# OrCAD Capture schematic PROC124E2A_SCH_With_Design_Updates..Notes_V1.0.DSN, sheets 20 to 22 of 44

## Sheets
20 18. eMMC FLASH: size C; title: eMMC FLASH INTERFACE
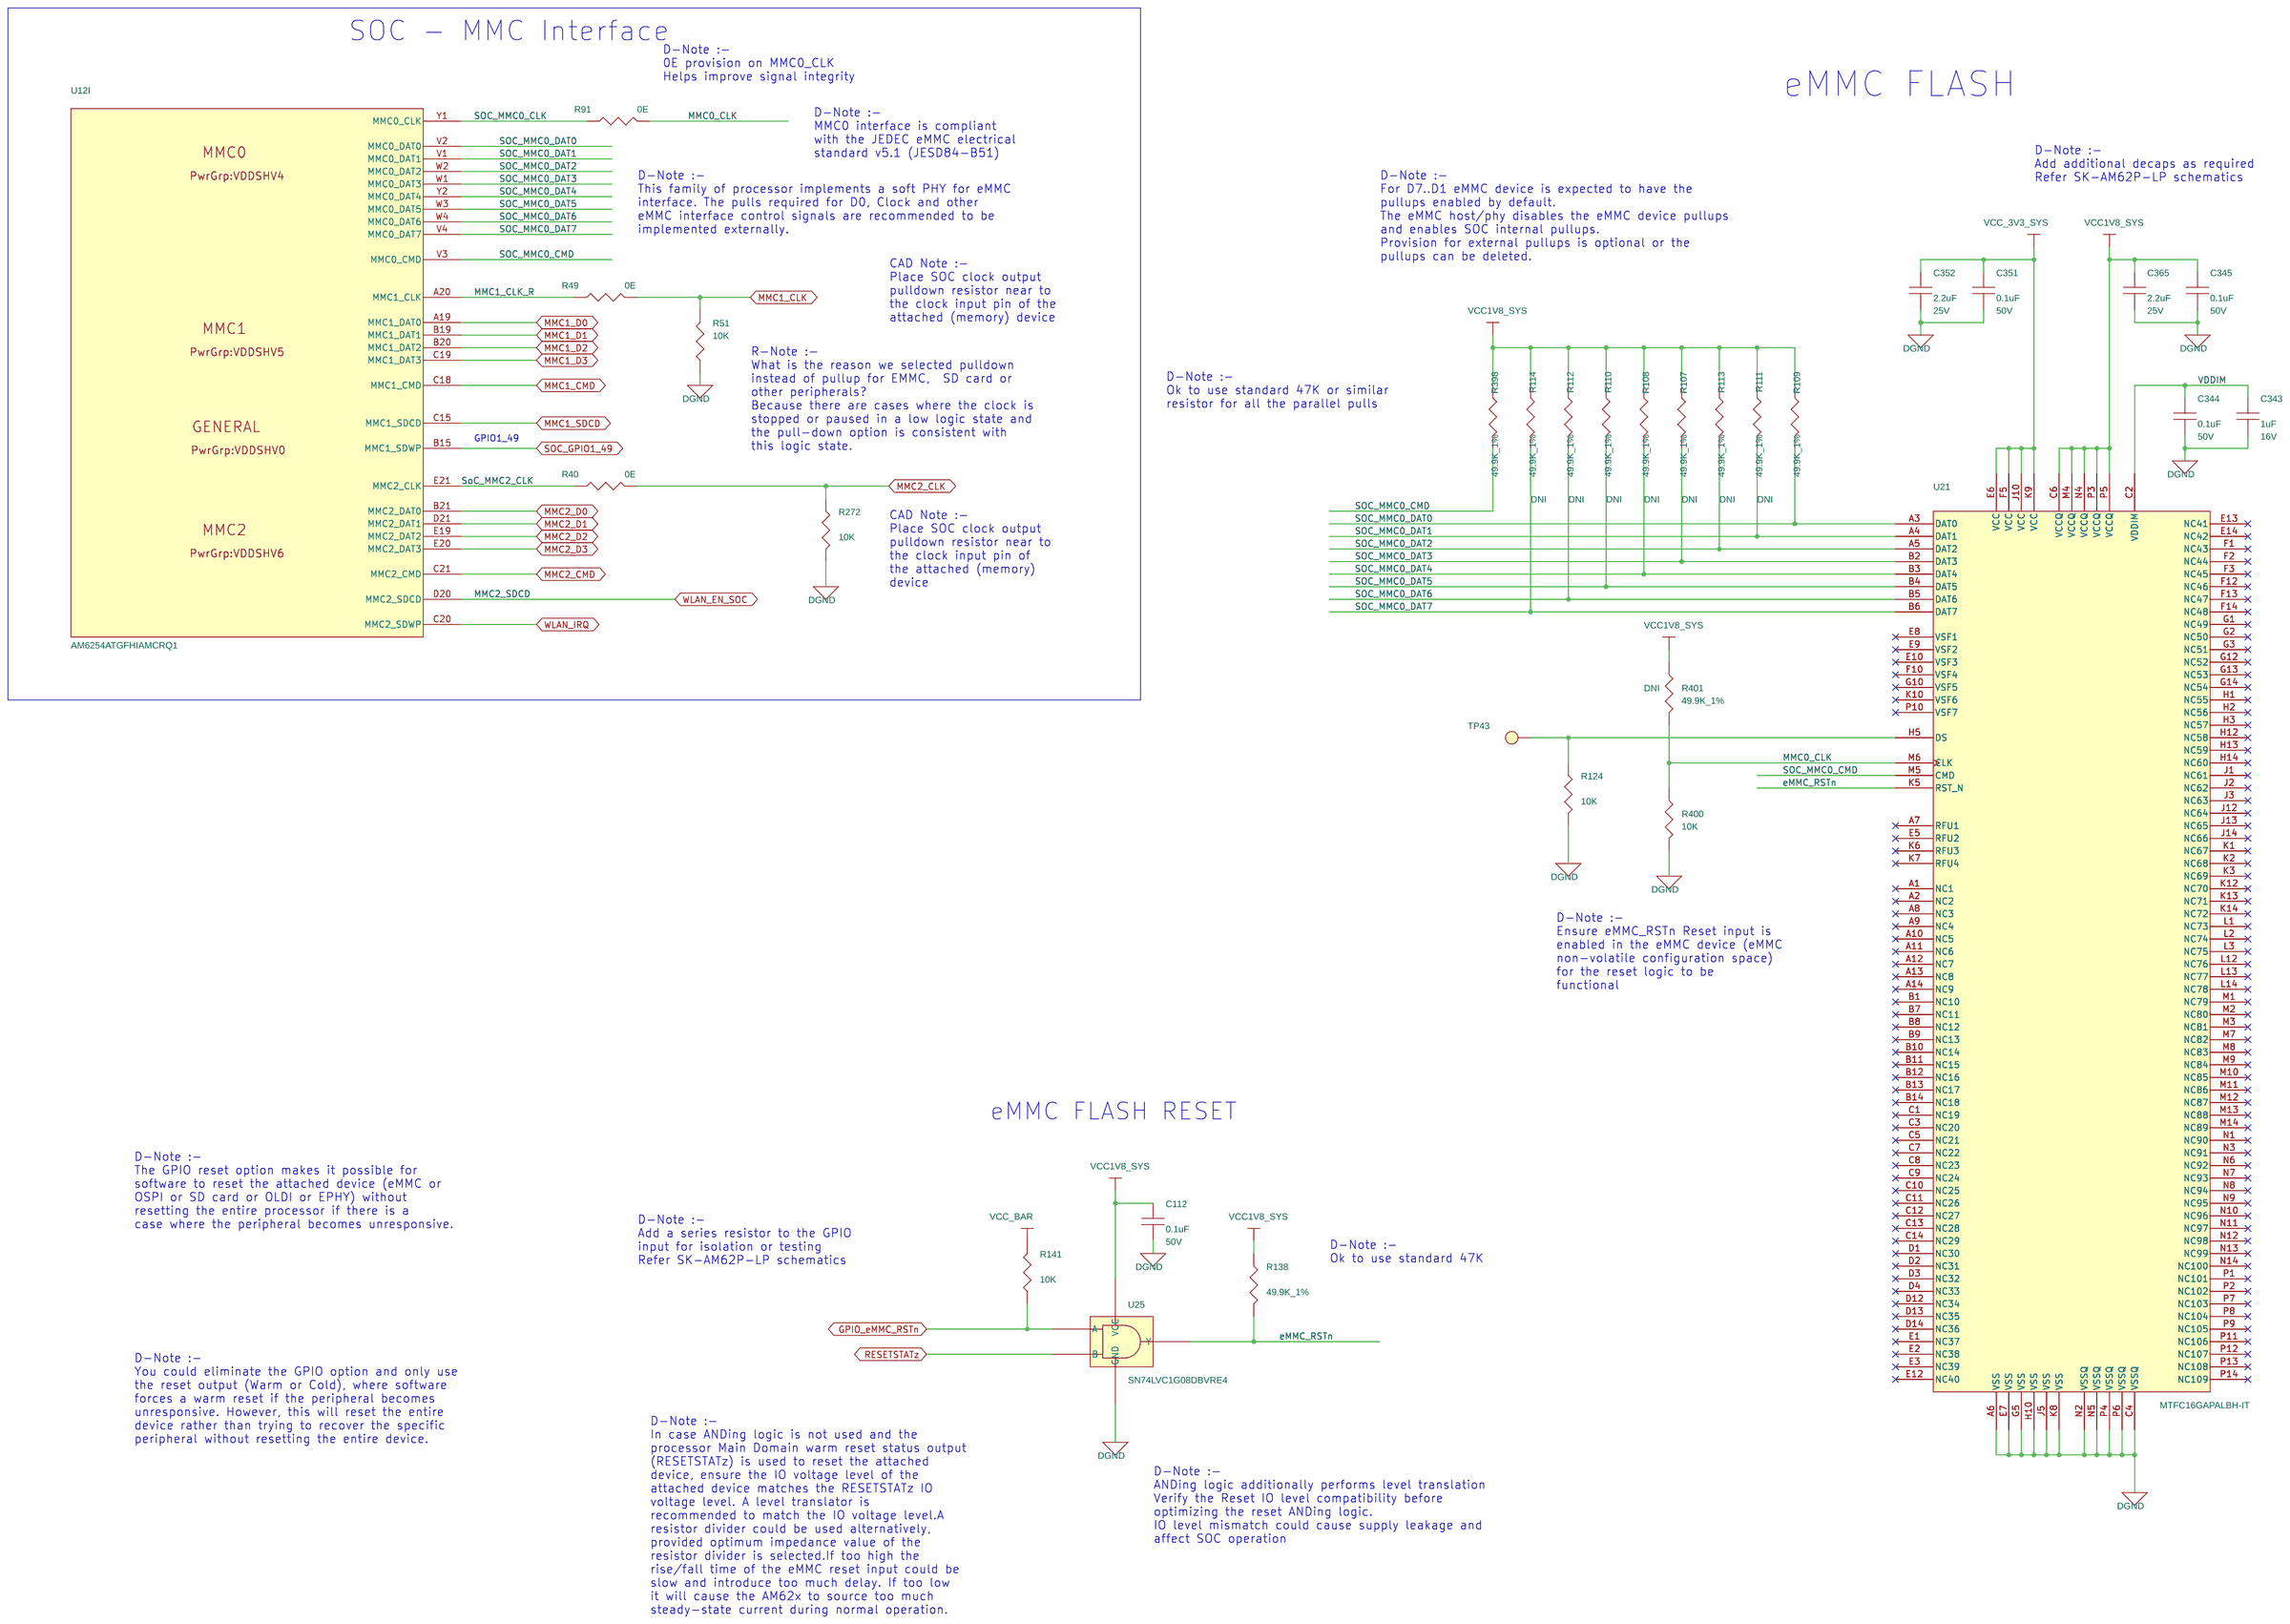
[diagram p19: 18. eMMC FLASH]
21 19. SD CARD INTERFACE: size C; title: SD CARD INTERFACE
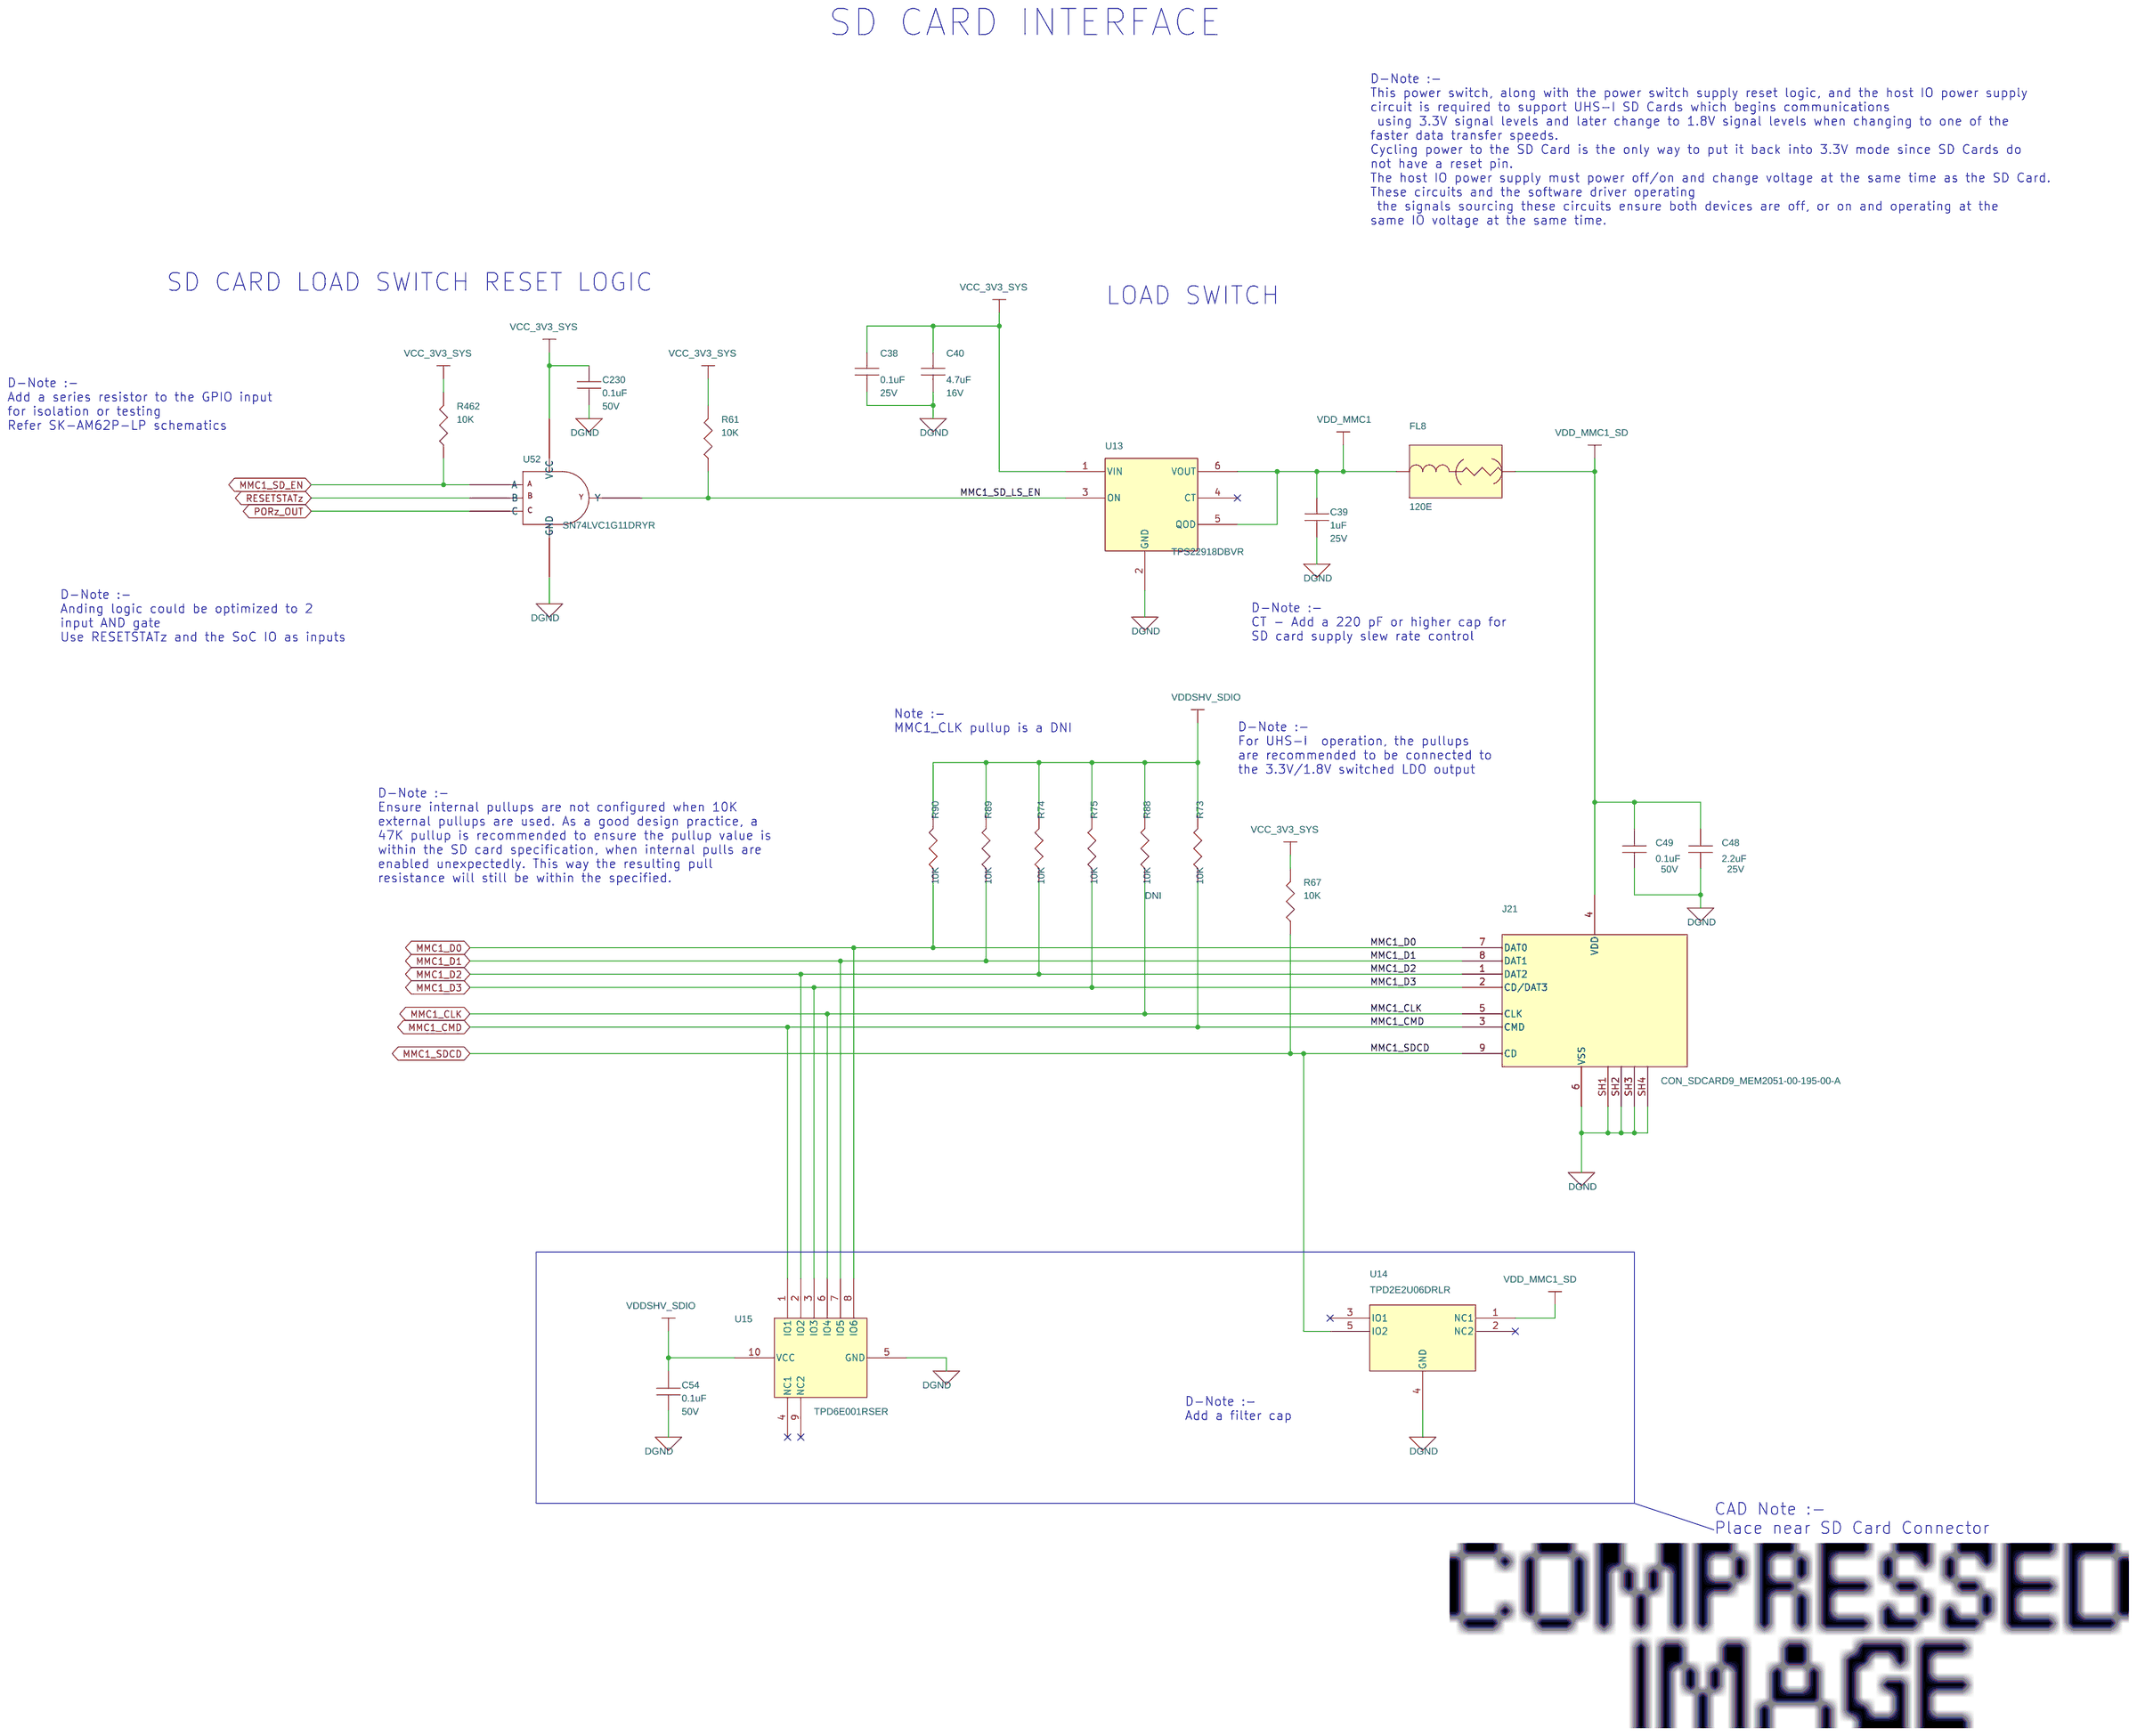
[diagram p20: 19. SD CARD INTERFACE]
22 20. OSPI INTERFACE: size C; title: OSPI INTERFACE
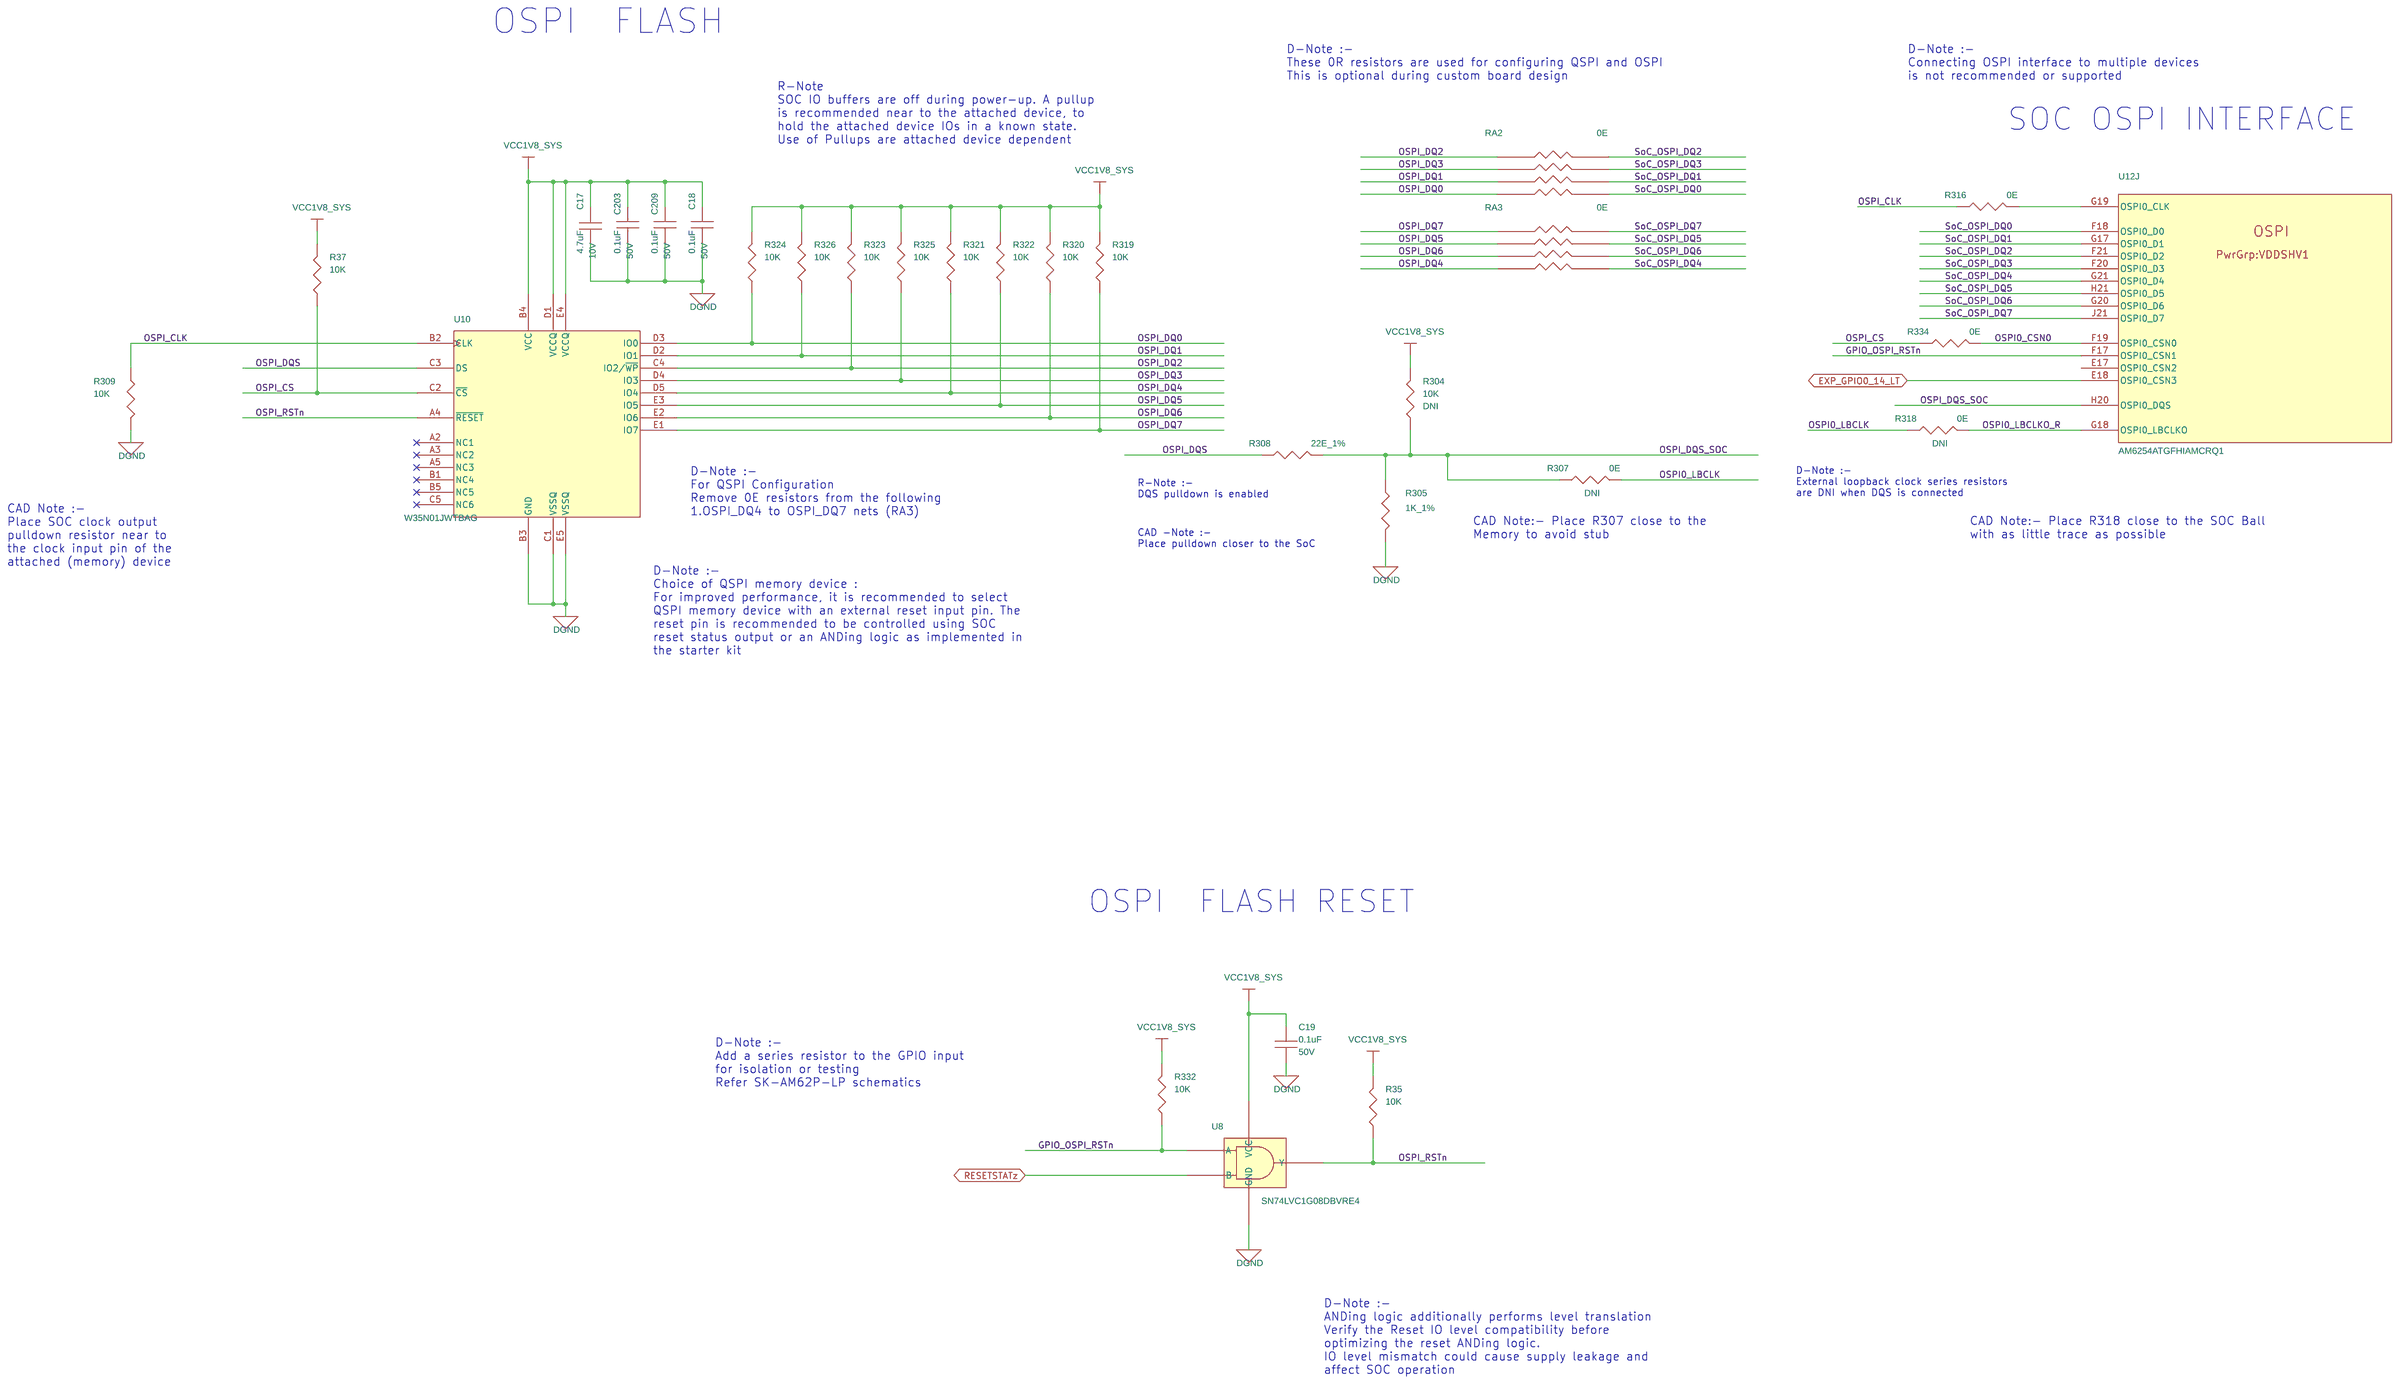
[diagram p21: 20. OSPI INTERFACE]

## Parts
sheet 15. SOC POWER CAPS
U12  AM6254ATGFHIAMCRQ1  [FCBGA441_31-49_680X680_2-6]  (sections A,B,C,D,E,F,G,H,I,J,K,L,M,N,O,P,Q,R)
sheet 18. eMMC FLASH
C112  0.1uF  [CAP0402_0-75]
C343  1uF  [CAP0201_0-5]
C344  0.1uF  [CAP0402_0-75]
C345  0.1uF  [CAP0402_0-75]
C351  0.1uF  [CAP0402_0-75]
C352  2.2uF  [CAP0402_0-75]
C365  2.2uF  [CAP0402_0-75]
R40  0E  [RES0201_0-5]
R49  0E  [RES0201_0-5]
R51  10K  [RES0201_0-5]
R91  0E  [RES0201_0-5]
R107  49.9K_1%  [RES0201_0-5]
R108  49.9K_1%  [RES0201_0-5]
R109  49.9K_1%  [RES0201_0-5]
R110  49.9K_1%  [RES0201_0-5]
R111  49.9K_1%  [RES0201_0-5]
R112  49.9K_1%  [RES0201_0-5]
R113  49.9K_1%  [RES0201_0-5]
R114  49.9K_1%  [RES0201_0-5]
R124  10K  [RES0201_0-5]
R138  49.9K_1%  [RES0201_0-5]
R141  10K  [RES0201_0-5]
R272  10K  [RES0201_0-5]
R398  49.9K_1%  [RES0201_0-5]
R400  10K  [RES0201_0-5]
R401  49.9K_1%  [RES0201_0-5]
TP43  TP20_SMD  [TP20_SMD]
U21  MTFC16GAPALBH-IT  [VFBGA153_19-68_460X520_1-1]
U25  SN74LVC1G08DBVRE4  [SOT23-5]
sheet 19. SD CARD INTERFACE
C38  0.1uF  [CAP0201_0-5]
C39  1uF  [CAP0402_0-75]
C40  4.7uF  [CAP0402_0-75]
C48  2.2uF  [CAP0402_0-75]
C49  0.1uF  [CAP0402_0-75]
C54  0.1uF  [CAP0402_0-75]
C230  0.1uF  [CAP0402_0-75]
FL8  120E  [EMIFIL_BLM15A_0402_0-6]
J21  CON_SDCARD9_MEM2051-00-195-00-A  [CON_SD9_MEM2051-00-195-00_S_R_S_2-1]
R61  10K  [RES0201_0-5]
R67  10K  [RES0201_0-5]
R73  10K  [RES0201_0-5]
R74  10K  [RES0201_0-5]
R75  10K  [RES0201_0-5]
R88  10K  [RES0201_0-5]
R89  10K  [RES0201_0-5]
R90  10K  [RES0201_0-5]
R462  10K  [RES0201_0-5]
U13  TPS22918DBVR  [SOT23-6]
U14  TPD2E2U06DRLR  [SOT553-5_0-6]
U15  TPD6E001RSER  [UQFN10_19-68_80X60_0-6]
U52  SN74LVC1G11DRYR  [SON6_SN74LVC2G17_40X60_0-6]
sheet 20. OSPI INTERFACE
C17  4.7uF  [CAP0402_0-75]
C18  0.1uF  [CAP0402_0-75]
C19  0.1uF  [CAP0402_0-75]
C203  0.1uF  [CAP0402_0-75]
C209  0.1uF  [CAP0402_0-75]
R35  10K  [RES0201_0-5]
R37  10K  [RES0201_0-5]
R304  10K  [RES0201_0-5]
R305  1K_1%  [RES0201_0-5]
R307  0E  [RES0201_0-5]
R308  22E_1%  [RES0201_0-5]
R309  10K  [RES0201_0-5]
R316  0E  [RES0402_0-5]
R318  0E  [RES0201_0-5]
R319  10K  [RES0201_0-5]
R320  10K  [RES0201_0-5]
R321  10K  [RES0201_0-5]
R322  10K  [RES0201_0-5]
R323  10K  [RES0201_0-5]
R324  10K  [RES0201_0-5]
R325  10K  [RES0201_0-5]
R326  10K  [RES0201_0-5]
R332  10K  [RES0201_0-5]
R334  0E  [RES0201_0-5]
RA2  0E  [RESA_EXB_0201-4_0-5]
RA3  0E  [RESA_EXB_0201-4_0-5]
U8  SN74LVC1G08DBVRE4  [SOT23-5]
U10  W35N01JWTBAG  [TPBGA24_39-37_240X320_1-2]

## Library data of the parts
U12 = AM6254ATGFHIAMCRQ1_FCBGA441: IC AM62Q SoC MICROPROCESSOR FCBGA441; Chkd/date: PRADEEP/180324; Crtd /date: TAMILARASU/180324; Custom_Duty: 15%; Customs_HS_Code: 85423100; Distributor_name: NA; Distributor_part_number: NA; Footprint Path: Y:\MIS_DATABASE\Library\ALTIUM_TOOL\PCB_FOOTPRINTS\Altium_Footprint_Lib.PcbLib; Height: 2.57MM; Library Path: Y:\MIS_DATABASE\Library\ALTIUM_TOOL\SCHEMATICS_PARTS\MS_MICROPROCESSOR_Library.schlib; Mfr_name: TEXAS INSTRUMENTS; Mistral Part No: 141224030001-R; Package: FCBGA441; Part_type: ICS\DIGITAL\MICROPROCESSOR; Project: TI_AM62Q_BRD; RoHS: NA; Temperature: NA; Tolerance: NA; Voltage: NA; Wattage: NA; Weight: NA; Datasheet: Y:\MIS_DATABASE\DATASHEETS\ICS\DIGITAL\MICROCONTROLLER\AM62Q-SoC.PDF
C18 C19 C49 C54 C112 C203 C209 C230 C344 C345 C351 = CAP: CAP CERAMIC 0.1uF 50V 10% X7R 0402; Alt_Mfr_name: YAGEO AMERICA; Alt_Mfr_part_number: CC0402KRX5R8BB104; Chkd/date: MANIRAJA/261020; Crtd /date: ALVY/211020; Custom_Duty: 15%; Customs_HS_Code: 85322990; Distributor_name: DIGIKEY; Distributor_part_number: 490-10700-1-ND; Footprint Path: Y:\MIS_DATABASE\Library\ALTIUM_TOOL\PCB_FOOTPRINTS\Altium_Footprint_Lib.PcbLib; Height: 0.55MM; Library Path: Y:\MIS_DATABASE\Library\ALTIUM_TOOL\SCHEMATICS_PARTS\MS_DISCRETE_Library.schlib; Mfr_name: MURATA; Mfr_part_number: GRM155R71H104KE14D; Mistral Part No: 120011100014-R; Package: 0402; Part_type: CAPACITORS\CERAMIC; Project: J7_CP; RoHS: RoHS; Temperature: -55°C+125°C; Tolerance: 10%; Voltage: 50V; Wattage: NA; Weight: 3.1mg; Datasheet: Y:\MIS_DATABASE\DATASHEETS\CAPACITORS\GRM155R71H104KE14.PDF
C343 = CAP: CAP CERAMIC 1uF 16V 20% X5R 0201; Chkd/date: MANIRAJA/300520; Crtd /date: ALVY/260520; Custom_Duty: 15%; Customs_HS_Code: 85322990; Distributor_name: DIGIKEY; Distributor_part_number: 490-18654-1-ND; Footprint Path: Y:\MIS_DATABASE\Library\ALTIUM_TOOL\PCB_FOOTPRINTS\Altium_Footprint_Lib.PcbLib; Height: 0.39MM; Library Path: Y:\MIS_DATABASE\Library\ALTIUM_TOOL\SCHEMATICS_PARTS\MS_DISCRETE_Library.schlib; Mfr_name: MURATA; Mfr_part_number: GRM033R61C105ME15D; Mistral Part No: 120018090038-R; Package: 0201; Part_type: CAPACITORS\CERAMIC; Project: QCS610_NANOSOM; RoHS: RoHS; Temperature: -55°C+85°C; Tolerance: 20%; Voltage: 16V; Wattage: NA; Weight: 0.33mg; Datasheet: Y:\MIS_DATABASE\DATASHEETS\CAPACITORS\GRM033R61C105ME15.PDF
C48 C352 C365 = CAP: CAP CERAMIC 2.2uF 25V 10% X5R 0402; Chkd/date: ALVY/010721; Crtd /date: MANIRAJA/010721; Custom_Duty: 15%; Customs_HS_Code: 85322990; Distributor_name: DIGIKEY; Distributor_part_number: 490-12703-1-ND; Footprint Path: Y:\MIS_DATABASE\Library\ALTIUM_TOOL\PCB_FOOTPRINTS\Altium_Footprint_Lib.PcbLib; Height: 0.70MM; Library Path: Y:\MIS_DATABASE\Library\ALTIUM_TOOL\SCHEMATICS_PARTS\MS_DISCRETE_Library.schlib; Mfr_name: MURATA; Mfr_part_number: GRM155R61E225KE11D; Mistral Part No: 120015120001-R; Package: 0402; Part_type: CAPACITORS\CERAMIC; Project: TI_AM263X_CC; RoHS: RoHS; Temperature: -55°C+85°C; Tolerance: 10%; Voltage: 25V; Wattage: NA; Weight: 1.5mg; Datasheet: Y:\MIS_DATABASE\DATASHEETS\CAPACITORS\GRM155R61E225KE11.PDF
R40 = RESISTOR: RES 0E 1/20W 5% 0201; Chkd/date: NAVEED/301214; Crtd /date: MUDDU/120710; Custom_Duty: 15%; Customs_HS_Code: 85332119; Distributor_name: DIGIKEY; Distributor_part_number: 311-0.0NCT-ND; Footprint Path: Y:\MIS_DATABASE\Library\ALTIUM_TOOL\PCB_FOOTPRINTS\Altium_Footprint_Lib.PcbLib; Height: 0.26MM; Library Path: Y:\MIS_DATABASE\Library\ALTIUM_TOOL\SCHEMATICS_PARTS\MS_DISCRETE_Library.schlib; Mfr_name: YAGEO AMERICA; Mfr_part_number: RC0201JR-070RL; Mistral Part No: 110010070067-R; Package: 0201; Part_type: RESISTORS\FIXED; Project: PB_BUGBASE; RoHS: RoHS; SIGNAL_MODEL: RESISTOR_RES0201_0-5_0E_0E; Temperature: -55°C+125°C; Tolerance: 5%; Voltage: NA; Wattage: 1/20W; Weight: 0.17mg; Datasheet: Y:\MIS_DATABASE\DATASHEETS\RESISTORS\RCXXXXL-SER_MAR18.PDF
R49 R91 R334 = RESISTOR: RES 0E 1/20W 5% 0201; Chkd/date: NAVEED/301214; Crtd /date: MUDDU/120710; Custom_Duty: 15%; Customs_HS_Code: 85332119; Distributor_name: DIGIKEY; Distributor_part_number: 311-0.0NCT-ND; Footprint Path: Y:\MIS_DATABASE\Library\ALTIUM_TOOL\PCB_FOOTPRINTS\Altium_Footprint_Lib.PcbLib; Height: 0.26MM; Library Path: Y:\MIS_DATABASE\Library\ALTIUM_TOOL\SCHEMATICS_PARTS\MS_DISCRETE_Library.schlib; Mfr_name: YAGEO AMERICA; Mfr_part_number: RC0201JR-070RL; Mistral Part No: 110010070067-R; Package: 0201; Part_type: RESISTORS\FIXED; Project: PB_BUGBASE; RoHS: RoHS; Temperature: -55°C+125°C; Tolerance: 5%; Voltage: NA; Wattage: 1/20W; Weight: 0.17mg; Datasheet: Y:\MIS_DATABASE\DATASHEETS\RESISTORS\RCXXXXL-SER_MAR18.PDF
R35 R37 R51 R61 R67 R73-R75 R89 R90 R124 R141 R272 R309 R319-R326 R332 R400 R462 = RESISTOR: RES 10K 1/20W 5% 0201; Chkd/date: MANIRAJA/050517; Crtd /date: MANIRAJA/050517; Custom_Duty: 15%; Customs_HS_Code: 85332119; Distributor_name: DIGIKEY; Distributor_part_number: 311-10KNCT-ND; Footprint Path: Y:\MIS_DATABASE\Library\ALTIUM_TOOL\PCB_FOOTPRINTS\Altium_Footprint_Lib.PcbLib; Height: 0.26MM; Library Path: Y:\MIS_DATABASE\Library\ALTIUM_TOOL\SCHEMATICS_PARTS\MS_DISCRETE_Library.schlib; Mfr_name: YAGEO AMERICA; Mfr_part_number: RC0201JR-0710KL; Mistral Part No: 110010070051-R; Package: 0201; Part_type: RESISTORS\FIXED; Project: GOLDEN-I LITE; RoHS: RoHS; Temperature: -55°C+125°C; Tolerance: 5%; Voltage: NA; Wattage: 1/20W; Weight: 0.17mg; Datasheet: Y:\MIS_DATABASE\DATASHEETS\RESISTORS\RCXXXXL-SER_MAR18.PDF
R107 R108 R110-R114 R401 = RESISTOR: RES 49.9K 1/20W 1% 0201; Assembly_Instruction: DNI; Chkd/date: PRAVEEN/080922; Crtd /date: TAMILARASU/080922; Custom_Duty: 15%; Customs_HS_Code: 85332119; Distributor_name: DIGIKEY; Distributor_part_number: P123047CT-ND; Footprint Path: Y:\MIS_DATABASE\Library\ALTIUM_TOOL\PCB_FOOTPRINTS\Altium_Footprint_Lib.PcbLib; Height: 0.26MM; Library Path: Y:\MIS_DATABASE\Library\ALTIUM_TOOL\SCHEMATICS_PARTS\MS_DISCRETE_Library.schlib; Mfr_name: PANASONIC-ECG; Mfr_part_number: ERJ-1GNF4992C; Mistral Part No: 110022090006-R; Package: 0201; Part_type: RESISTORS\FIXED; Project: SK AM62Q LP EVM BRD; RoHS: RoHS; Temperature: -55°C+125°C; Tolerance: 1%; Voltage: NA; Wattage: 1/20W; Weight: 0.15mg; Datasheet: Y:\MIS_DATABASE\DATASHEETS\RESISTORS\PAN-ERJSER_NOV17.PDF
R109 R138 R398 = RESISTOR: RES 49.9K 1/20W 1% 0201; Chkd/date: PRAVEEN/080922; Crtd /date: TAMILARASU/080922; Custom_Duty: 15%; Customs_HS_Code: 85332119; Distributor_name: DIGIKEY; Distributor_part_number: P123047CT-ND; Footprint Path: Y:\MIS_DATABASE\Library\ALTIUM_TOOL\PCB_FOOTPRINTS\Altium_Footprint_Lib.PcbLib; Height: 0.26MM; Library Path: Y:\MIS_DATABASE\Library\ALTIUM_TOOL\SCHEMATICS_PARTS\MS_DISCRETE_Library.schlib; Mfr_name: PANASONIC-ECG; Mfr_part_number: ERJ-1GNF4992C; Mistral Part No: 110022090006-R; Package: 0201; Part_type: RESISTORS\FIXED; Project: SK AM62Q LP EVM BRD; RoHS: RoHS; Temperature: -55°C+125°C; Tolerance: 1%; Voltage: NA; Wattage: 1/20W; Weight: 0.15mg; Datasheet: Y:\MIS_DATABASE\DATASHEETS\RESISTORS\PAN-ERJSER_NOV17.PDF
TP43 = TESTPOINT: TESTPOINT CIR 20 SMD; Chkd/date: SHREESHAIL/171006; Crtd /date: MAZHAR/171006; Custom_Duty: NA; Customs_HS_Code: NA; Distributor_name: NA; Distributor_part_number: NA; Footprint Path: Y:\MIS_DATABASE\Library\ALTIUM_TOOL\PCB_FOOTPRINTS\Altium_Footprint_Lib.PcbLib; Height: NA; Library Path: Y:\MIS_DATABASE\Library\ALTIUM_TOOL\SCHEMATICS_PARTS\MS_DISCRETE_Library.schlib; MECHANICAL 3D STEP FILE: NA; Mfr_name: LOCAL; Mistral Part No: NA; Package: SMD; Project: BT MODULE_CSRBC04; RoHS: NA; Temperature: NA; Tolerance: NA; Voltage: NA; Wattage: NA; Weight: NA; Datasheet: NA
U21 = MTFC16GAPALBH_TFBGA153: IC 16GB e-MMC MEMORY TFBGA153; Chkd/date: MANIRAJA/070220; Crtd /date: ALVY/070220; Custom_Duty: 15%; Customs_HS_Code: 85423100; Distributor_name: DIGIKEY; Distributor_part_number: MTFC16GAPALBH-IT-ND; Footprint Path: Y:\MIS_DATABASE\Library\ALTIUM_TOOL\PCB_FOOTPRINTS\Altium_Footprint_Lib.PcbLib; Height: 1.10MM; Library Path: Y:\MIS_DATABASE\Library\ALTIUM_TOOL\SCHEMATICS_PARTS\MS_MISCMEMORY_Library.schlib; Mfr_name: MICRON; Mistral Part No: 141120020001-R; Package: TFBGA153; Part_type: ICS\DIGITAL\MEMORY; Project: TI_MAXIE_CPB; RoHS: RoHS; Temperature: -40°C+85°C; Tolerance: NA; Voltage: NA; Wattage: NA; Weight: NA; Datasheet: Y:\MIS_DATABASE\DATASHEETS\ICS\MEMORY\MTFCXX-IT.PDF
U8 U25 = SN74LVC1G08DBVRE4_SOT23-5: IC SINGLE 2-INPUT POSITIVE AND GATE SOT23-5; Chkd/date: SUHAS/221010; Crtd /date: USMAN/151008; Custom_Duty: 15%; Customs_HS_Code: 85423100; Distributor_name: DIGIKEY; Distributor_part_number: SN74LVC1G08DBVRE4-ND; Height: 1.45MM; Mfr_name: TEXAS INSTRUMENTS; Mistral Part No: 141009060026-R; Part_type: ICS\DIGITAL\GATES; Project: KHAN_MAIN; RoHS: Sb/ Br FREE; Temperature: -40°C+85°C; Datasheet: Y:\MIS_DATABASE\DATASHEETS\ICS\DIGITAL\GATES\SN74LVC1G08.PDF
C38 = CAP: CAP CERAMIC 0.1uF 25V 10% X5R 0201; Chkd/date: PRAVEEN/131222; Crtd /date: TAMILARASU/131222; Custom_Duty: 15%; Customs_HS_Code: 85322990; Distributor_name: DIGIKEY; Distributor_part_number: 490-12686-1-ND; Footprint Path: Y:\MIS_DATABASE\Library\ALTIUM_TOOL\PCB_FOOTPRINTS\Altium_Footprint_Lib.PcbLib; Height: 0.33MM; Library Path: Y:\MIS_DATABASE\Library\ALTIUM_TOOL\SCHEMATICS_PARTS\MS_DISCRETE_Library.schlib; Mfr_name: MURATA; Mfr_part_number: GRM033R61E104KE14D; Mistral Part No: 120022120017-R; Package: 0201; Part_type: CAPACITORS\CERAMIC; Project: CLOUD RADAR; RoHS: RoHS; Temperature: -55°C+85°C; Tolerance: 10%; Voltage: 25V; Wattage: NA; Weight: 0.33mg; Datasheet: Y:\MIS_DATABASE\DATASHEETS\CAPACITORS\GRM033R61E104KE14D.PDF
C39 = CAP: CAP CERAMIC 1uF 25V 10% X5R AUTO 0402; Chkd/date: MANIRAJA/290318; Crtd /date: ALVY/280318; Custom_Duty: 15%; Customs_HS_Code: 85322990; Distributor_name: DIGIKEY; Distributor_part_number: 490-12263-1-ND; Footprint Path: Y:\MIS_DATABASE\Library\ALTIUM_TOOL\PCB_FOOTPRINTS\Altium_Footprint_Lib.PcbLib; Height: 0.55MM; Library Path: Y:\MIS_DATABASE\Library\ALTIUM_TOOL\SCHEMATICS_PARTS\MS_DISCRETE_Library.schlib; Mfr_name: MURATA; Mfr_part_number: GRT155R61E105KE01D; Mistral Part No: 120019040035-R; Package: 0402; Part_type: CAPACITORS\CERAMIC; Project: NPOL_SAR_ADC; RoHS: RoHS; Temperature: -55°C+85°C; Tolerance: 10%; Voltage: 25V; Wattage: NA; Weight: 0.65mg; Datasheet: Y:\MIS_DATABASE\DATASHEETS\CAPACITORS\GRT155R61E105KE01D.PDF
C40 = CAP: CAP CERAMIC 4.7uF 16V 20% X5R 0402; Alt_Mfr_name: YAGEO AMERICA; Alt_Mfr_part_number: CC0402KRX5R8BB104; Chkd/date: MANIRAJA/061218; Crtd /date: ALVY/061218; Custom_Duty: 15%; Customs_HS_Code: 85322990; Distributor_name: DIGIKEY; Distributor_part_number: 311-3482-1-ND; Footprint Path: Y:\MIS_DATABASE\Library\ALTIUM_TOOL\PCB_FOOTPRINTS\Altium_Footprint_Lib.PcbLib; Height: 0.65MM; Library Path: Y:\MIS_DATABASE\Library\ALTIUM_TOOL\SCHEMATICS_PARTS\MS_DISCRETE_Library.schlib; Mfr_name: YAGEO AMERICA; Mfr_part_number: CC0402MRX5R7BB475; Mistral Part No: 120017100010-R; Package: 0402; Part_type: CAPACITORS\CERAMIC; Project: RFSU_POC-CARD; RoHS: RoHS; Temperature: -55°C+85°C; Tolerance: 20%; Voltage: 16V; Wattage: NA; Weight: NA; Datasheet: Y:\MIS_DATABASE\DATASHEETS\CAPACITORS\YACC-X5R.PDF
FL8 = EMIFILTER_IND: IND FERRITE BEAD CHIP 120E 2A 0402; Chkd/date: NAVEED/241114; Crtd /date: USMAN/170613; Custom_Duty: 24%; Customs_HS_Code: 85369090; Distributor_name: DIGIKEY; Distributor_part_number: 490-9656-1-ND; Footprint Path: Y:\MIS_DATABASE\Library\ALTIUM_TOOL\PCB_FOOTPRINTS\Altium_Footprint_Lib.PcbLib; Height: 0.55MM; Library Path: Y:\MIS_DATABASE\Library\ALTIUM_TOOL\SCHEMATICS_PARTS\MS_FILTER_Library.schlib; Mfr_name: MURATA; Mfr_part_number: BLM15PX121SN1D; Mistral Part No: 130013060022-R; Package: 0402; Part_type: INDUCTOR; Project: GEN_3-8; RoHS: RoHS; Temperature: -55°C+125°C; Tolerance: 25%; Voltage: NA; Wattage: NA; Weight: 1mg; Datasheet: Y:\MIS_DATABASE\DATASHEETS\DISCRETES\INDUCTORS\BLM15-SN1-SER.PDF
J21 = CON_SDCARD9_MEM2075-00-140: CON MICROSD CARD 9POS FEMALE RT SMD; Chkd/date: MANIRAJA/270921; Crtd /date: ALVY/240921; Custom_Duty: 24%; Customs_HS_Code: 85369090; Distributor_name: DIGIKEY; Distributor_part_number: 2073-MEM2051-00-195-00-ACT-ND; Footprint Path: Y:\MIS_DATABASE\Library\ALTIUM_TOOL\PCB_FOOTPRINTS\Altium_Footprint_Lib.PcbLib; Height: 2.05MM; Library Path: Y:\MIS_DATABASE\Library\ALTIUM_TOOL\SCHEMATICS_PARTS\MS_CONNECTOR_Library.schlib; Mfr_name: GCT; Mfr_part_number: MEM2051-00-195-00-A; Mistral Part No: 150021090028-R; Package: SMD; Part_type: CONNECTOR\MEMORY CARD; Project: TI_AM62x SKEVM_BRD; RoHS: RoHS; Temperature: -40°C+85°C; Tolerance: NA; Voltage: NA; Wattage: NA; Weight: 1000mg; Datasheet: Y:\MIS_DATABASE\DATASHEETS\CONNECTORS\MEM2051-00-195-00-A.PDF
R88 R304 = RESISTOR: RES 10K 1/20W 5% 0201; Assembly_Instruction: DNI; Chkd/date: MANIRAJA/050517; Crtd /date: MANIRAJA/050517; Custom_Duty: 15%; Customs_HS_Code: 85332119; Distributor_name: DIGIKEY; Distributor_part_number: 311-10KNCT-ND; Footprint Path: Y:\MIS_DATABASE\Library\ALTIUM_TOOL\PCB_FOOTPRINTS\Altium_Footprint_Lib.PcbLib; Height: 0.26MM; Library Path: Y:\MIS_DATABASE\Library\ALTIUM_TOOL\SCHEMATICS_PARTS\MS_DISCRETE_Library.schlib; Mfr_name: YAGEO AMERICA; Mfr_part_number: RC0201JR-0710KL; Mistral Part No: 110010070051-R; Package: 0201; Part_type: RESISTORS\FIXED; Project: GOLDEN-I LITE; RoHS: RoHS; Temperature: -55°C+125°C; Tolerance: 5%; Voltage: NA; Wattage: 1/20W; Weight: 0.17mg; Datasheet: Y:\MIS_DATABASE\DATASHEETS\RESISTORS\RCXXXXL-SER_MAR18.PDF
U13 = TPS22918DBVR_SOT23-6: IC ON RESISTANCE LOAD SWITCH SOT23-6; Automotive Alternate_mfr_name: TEXAS INSTRUMENTS; Automotive Alternate_mfr_part_number: TPS22918TDBVRQ1; Chkd/date: VASANTHA/130516; Crtd /date: VASANTHA/130516; Custom_Duty: 15%; Customs_HS_Code: 85423100; Distributor_name: DIGIKEY; Distributor_part_number: TPS22918DBVR-ND; Height: 1.45MM; Mfr_name: TEXAS INSTRUMENTS; Mistral Part No: 142016050007-R; Part_type: ICS\POWER; Project: TMDXCSK8127; RoHS: RoHS; Temperature: -40°C to 105°C; Tolerance: NA; Voltage: NA; Wattage: NA; Weight: NA; Datasheet: Y:\MIS_DATABASE\DATASHEETS\ICS\POWER\TPS22918DBV.PDF
U14 = TPD2E2U06_SOT5X3-5: IC DUAL CHANNEL HIGH SPEED ESD PROTECTION SOT5X3-5; Chkd/date: PRAVEEN/130423; Crtd /date: PRAVEEN/130423; Custom_Duty: 15%; Customs_HS_Code: 85423100; Distributor_name: DIGIKEY; Distributor_part_number: 296-38361-1-ND; Footprint Path: Y:\MIS_DATABASE\Library\ALTIUM_TOOL\PCB_FOOTPRINTS\Altium_Footprint_Lib.PcbLib; Height: 0.60MM; Library Path: Y:\MIS_DATABASE\Library\ALTIUM_TOOL\SCHEMATICS_PARTS\MS_MISCINTERFACE_Library.schlib; Mfr_name: TEXAS INSTRUMENTS; Mistral Part No: 141023040006-R; Package: SOT5X3-5; Part_type: ICS\INTERFACE; Project: SK-AM62Q-LP_EVM; RoHS: RoHS; Temperature: -40°C+125°C; Tolerance: NA; Voltage: NA; Wattage: NA; Weight: 2.8mg; Datasheet: Y:\MIS_DATABASE\DATASHEETS\ICS\INTERFACE\TPD2E2U06.PDF
U15 = TPD6E001RSE_UQFN10: IC 6CH ESD-PROTECTION ARRAY UQFN10; Chkd/date: USMAN/070612; Crtd /date: BAVISH/160811; Custom_Duty: 15%; Customs_HS_Code: 85423100; Distributor_name: DIGIKEY; Distributor_part_number: 296-21888-1-ND; Footprint Path: Y:\MIS_DATABASE\Library\ALTIUM_TOOL\PCB_FOOTPRINTS\Altium_Footprint_Lib.PcbLib; Height: 0.60MM; IBISSP_MODLES: Y:\MIS_DATABASE\IBIS\ICs\INTERFACE\TPD6E001RSE.IBS; Library Path: Y:\MIS_DATABASE\Library\ALTIUM_TOOL\SCHEMATICS_PARTS\MS_MISCINTERFACE_Library.schlib; Mfr_name: TEXAS INSTRUMENTS; Mistral Part No: 141011080020-R; Package: UQFN10; Part_type: ICS\INTERFACE; Project: DM385EVM_BASE-BOARD; RoHS: RoHS; Temperature: -40°C+85°C; Tolerance: NA; Voltage: NA; Wattage: NA; Weight: 7mg; Datasheet: Y:\MIS_DATABASE\DATASHEETS\ICS\INTERFACE\TPD6E001.PDF
U52 = SN74LVC1G11DCKR_SC70-6: IC SINGLE 3-INPUT POSITIVE-AND GATE SON6; Chkd/date: MANIRAJA/270121; Crtd /date: ALVY/270121; Custom_Duty: 15%; Customs_HS_Code: 85423100; Distributor_name: DIGIKEY; Distributor_part_number: 296-30120-1-ND; Footprint Path: Y:\MIS_DATABASE\Library\ALTIUM_TOOL\PCB_FOOTPRINTS\Altium_Footprint_Lib.PcbLib; Height: 0.60MM; Library Path: Y:\MIS_DATABASE\Library\ALTIUM_TOOL\SCHEMATICS_PARTS\MS_GATE_Library.schlib; Mfr_name: TEXAS INSTRUMENTS; Mistral Part No: 141021010013-R; Package: SON6; Part_type: ICS\DIGITAL\GATES; Project: AM64X_SKEVM; RoHS: RoHS; Temperature: -40°C+125°C; Tolerance: NA; Voltage: NA; Wattage: NA; Weight: 33mg; Datasheet: Y:\MIS_DATABASE\DATASHEETS\ICS\DIGITAL\GATES\SN74LVC1G_NOV16.PDF
C17 = CAP: CAP CERAMIC 4.7uF 10V 20% X5R 0402; Chkd/date: MANIRAJA/110718; Crtd /date: ALVY/110718; Custom_Duty: 15%; Customs_HS_Code: 85322990; Distributor_name: DIGIKEY; Distributor_part_number: 490-14306-1-ND; Footprint Path: Y:\MIS_DATABASE\Library\ALTIUM_TOOL\PCB_FOOTPRINTS\Altium_Footprint_Lib.PcbLib; Height: 0.65MM; Library Path: Y:\MIS_DATABASE\Library\ALTIUM_TOOL\SCHEMATICS_PARTS\MS_DISCRETE_Library.schlib; Mfr_name: MURATA; Mfr_part_number: GRM155R61A475MEAAD; Mistral Part No: 120012060002-R; Package: 0402; Part_type: CAPACITORS\CERAMIC; Project: TI_J7SVB_PCIE_ADD-ON-CARD; RoHS: RoHS; Temperature: -55°C+85°C; Tolerance: 20%; Voltage: 10V; Wattage: NA; Weight: 14mg; Datasheet: Y:\MIS_DATABASE\DATASHEETS\CAPACITORS\GRM155R61A475MEAAD.PDF
R305 = RESISTOR: RES 1K 1/20W 1% 0201; Chkd/date: JEBRAN/110815; Crtd /date: JEBRAN/110815; Custom_Duty: 15%; Customs_HS_Code: 85332119; Distributor_name: DIGIKEY; Distributor_part_number: 541-1.00KAABCT-ND; Footprint Path: Y:\MIS_DATABASE\Library\ALTIUM_TOOL\PCB_FOOTPRINTS\Altium_Footprint_Lib.PcbLib; Height: 0.28MM; Library Path: Y:\MIS_DATABASE\Library\ALTIUM_TOOL\SCHEMATICS_PARTS\MS_DISCRETE_Library.schlib; Mfr_name: VISHAY; Mfr_part_number: CRCW02011K00FKED; Mistral Part No: 110015080014-R; Package: 0201; Part_type: RESISTORS\FIXED; Project: OCTASIC_3000; RoHS: RoHS; Temperature: -55°C+155°C; Tolerance: 1%; Voltage: NA; Wattage: 1/20W; Weight: 0.17mg; Datasheet: Y:\MIS_DATABASE\DATASHEETS\RESISTORS\CRCW0201.PDF
R307 R318 = RESISTOR: RES 0E 1/20W 5% 0201; Assembly_Instruction: DNI; Chkd/date: NAVEED/301214; Crtd /date: MUDDU/120710; Custom_Duty: 15%; Customs_HS_Code: 85332119; Distributor_name: DIGIKEY; Distributor_part_number: 311-0.0NCT-ND; Footprint Path: Y:\MIS_DATABASE\Library\ALTIUM_TOOL\PCB_FOOTPRINTS\Altium_Footprint_Lib.PcbLib; Height: 0.26MM; Library Path: Y:\MIS_DATABASE\Library\ALTIUM_TOOL\SCHEMATICS_PARTS\MS_DISCRETE_Library.schlib; Mfr_name: YAGEO AMERICA; Mfr_part_number: RC0201JR-070RL; Mistral Part No: 110010070067-R; Package: 0201; Part_type: RESISTORS\FIXED; Project: PB_BUGBASE; RoHS: RoHS; SIGNAL_MODEL: RESISTOR_RES0201_0-5_0E_0E; Temperature: -55°C+125°C; Tolerance: 5%; Voltage: NA; Wattage: 1/20W; Weight: 0.17mg; Datasheet: Y:\MIS_DATABASE\DATASHEETS\RESISTORS\RCXXXXL-SER_MAR18.PDF
R308 = RESISTOR: RES 22E 1/20W 1% 0201; Chkd/date: PRAVEEN/080922; Crtd /date: TAMILARASU/080922; Custom_Duty: 15%; Customs_HS_Code: 85332119; Distributor_name: DIGIKEY; Distributor_part_number: P122843CT-ND; Footprint Path: Y:\MIS_DATABASE\Library\ALTIUM_TOOL\PCB_FOOTPRINTS\Altium_Footprint_Lib.PcbLib; Height: 0.26MM; Library Path: Y:\MIS_DATABASE\Library\ALTIUM_TOOL\SCHEMATICS_PARTS\MS_DISCRETE_Library.schlib; Mfr_name: PANASONIC-ECG; Mfr_part_number: ERJ-1GNF22R0C; Mistral Part No: 110022090007-R; Package: 0201; Part_type: RESISTORS\FIXED; Project: SK AM62Q LP EVM BRD; RoHS: RoHS; SIGNAL_MODEL: RESISTOR_RES0201_0-5_22E_1%_22E_1%; Temperature: -55°C+125°C; Tolerance: 1%; Voltage: NA; Wattage: 1/20W; Weight: 0.15mg; Datasheet: Y:\MIS_DATABASE\DATASHEETS\RESISTORS\PAN-ERJSER_NOV17.PDF
R316 = RESISTOR: RES 0E 1/16W JUMPER 0402; Chkd/date: VASANTHA/201216; Crtd /date: MUDDU/190810; Custom_Duty: 15%; Customs_HS_Code: 85332119; Distributor_name: DIGIKEY; Distributor_part_number: 541-0.0JCT-ND; Footprint Path: Y:\MIS_DATABASE\Library\ALTIUM_TOOL\PCB_FOOTPRINTS\Altium_Footprint_Lib.PcbLib; Height: 0.40MM; Library Path: Y:\MIS_DATABASE\Library\ALTIUM_TOOL\SCHEMATICS_PARTS\MS_DISCRETE_Library.schlib; Mfr_name: VISHAY; Mfr_part_number: CRCW04020000Z0ED; Mistral Part No: 110010080019-R; Package: 0402; Part_type: RESISTORS\FIXED; Project: PB_BUGBASE; RoHS: RoHS; SIGNAL_MODEL: RESISTOR_RES0402_0-5_0E_0E; Temperature: -55°C+155°C; Tolerance: NA; Voltage: NA; Wattage: 1/16W; Weight: 0.65mg; Datasheet: Y:\MIS_DATABASE\DATASHEETS\RESISTORS\CRCW0603.PDF
RA2 RA3 = RESARR_ISO4: RES ARRAY 0E 31mW JUMPER 0201-4; Chkd/date: MANIRAJA/290918; Crtd /date: MANIRAJA/290918; Custom_Duty: 15%; Customs_HS_Code: 85332119; Distributor_name: DIGIKEY; Distributor_part_number: Y6000CT-ND; Footprint Path: Y:\MIS_DATABASE\Library\ALTIUM_TOOL\PCB_FOOTPRINTS\Altium_Footprint_Lib.PcbLib; Height: 0.45MM; Library Path: Y:\MIS_DATABASE\Library\ALTIUM_TOOL\SCHEMATICS_PARTS\MS_DISCRETE_Library.schlib; Manufacturer: PANASONIC-ECG; Mfr_name: PANASONIC-ECG; Mfr_part_number: EXB-18VR000X; Mistral Part No: 110018090033-R; Package: 0201-4; Part_type: RESISTORS\ARRAY; Project: TI_60GHz-AOP; RoHS: RoHS; SIGNAL_MODEL: RESARR_ISO4_RESA_EXB_0201-4_0-5_0E; Temperature: -55°C+125°C; Tolerance: NA; Voltage: NA; Wattage: 31mW; Weight: 1mg; Datasheet: Y:\MIS_DATABASE\DATASHEETS\RESISTORS\EXB-18V.PDF
U10 = W35N01JWTB_TFBGA24: IC 1.7-1.95V 1Gb SERIAL SLC NAND FLASH MEMORY OCTAL SPI TFBGA24; Chkd/date: MANIRAJA/090421; Crtd /date: ALVY/080421; Custom_Duty: 15%; Customs_HS_Code: 85423100; Distributor_name: NA; Distributor_part_number: NA; Footprint Path: Y:\MIS_DATABASE\Library\ALTIUM_TOOL\PCB_FOOTPRINTS\Altium_Footprint_Lib.PcbLib; Height: 1.20MM; Library Path: Y:\MIS_DATABASE\Library\ALTIUM_TOOL\SCHEMATICS_PARTS\MS_MISCMEMORY_Library.schlib; Mfr_name: WINBOND; Mistral Part No: 141121040002-R; Package: TFBGA24; Part_type: ICS\DIGITAL\MEMORY; Project: TI_J7AEP SOM BRD; RoHS: RoHS; Temperature: -40°C+105°C; Tolerance: NA; Voltage: NA; Wattage: NA; Weight: NA; Datasheet: Y:\MIS_DATABASE\DATASHEETS\ICS\MEMORY\W35N01JWXX.PDF

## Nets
DGND: C17.1 C18.2 C19.2 C38.2 C39.2 C40.2 C48.1 C49.1 C54.1 C112.2 C203.2 C209.2 C230.2 C343.2 C344.2 C345.2 C351.2 C352.2 C365.2 J21.6(VSS) J21.SH1 J21.SH2 J21.SH3 J21.SH4 R51.2 R124.2 R272.2 R305.2 R309.2 R400.2 U8.3(GND) U10.B3(GND) U10.C1(VSSQ) U10.E5(VSSQ) U13.2(GND) U14.4(GND) U15.5(GND) U21.A6(VSS) U21.C4(VSSQ) U21.E7(VSS) U21.G5(VSS) U21.H10(VSS) U21.J5(VSS) U21.K8(VSS) U21.N2(VSSQ) U21.N5(VSSQ) U21.P4(VSSQ) U21.P6(VSSQ) U25.3(GND) U52.2(GND) ; also on sheet 1 2 3 4 13 14 15 16 17 18 19 23 24 25 26 27 28 29 30 31 32 33 34 35 36 37 38 39 40 41 42 43
VCC1V8_SYS: C17.2 C18.1 C19.1 C112.1 C203.1 C209.1 C345.1 C365.1 R35.2 R37.2 R107.1 R108.1 R109.1 R110.1 R111.1 R112.1 R113.1 R114.1 R138.1 R304.2 R319.2 R320.2 R321.2 R322.2 R323.2 R324.2 R325.2 R326.2 R332.2 R398.1 R401.1 U8.5(VCC) U10.B4(VCC) U10.D1(VCCQ) U10.E4(VCCQ) U21.C6(VCCQ) U21.M4(VCCQ) U21.N4(VCCQ) U21.P3(VCCQ) U21.P5(VCCQ) U25.5(VCC) ; also on sheet 4 16 19 25 34 37 39 40 42
VCC_3V3_SYS: C38.1 C40.1 C230.1 C351.1 C352.1 R61.2 R67.2 R141.2 R462.2 U13.1(VIN) U21.E6(VCC) U21.F5(VCC) U21.J10(VCC) U21.K9(VCC) U52.5(VCC) ; also on sheet 1 4 15 16 19 23 24 26 27 29 30 31 32 33 34 36 37 38 39 40 41 42 43
VDD_MMC1: C39.1 FL8.1 U13.5(QOD) U13.6(VOUT)
VDD_MMC1_SD: C48.2 C49.2 FL8.2 J21.4(VDD) U14.1(NC1)
VDDIM: C343.1 C344.1 U21.C2(VDDIM)
VDDSHV_SDIO: C54.2 R73.2 R74.2 R75.2 R88.2 R89.2 R90.2 U15.10(VCC) ; also on sheet 4 17
eMMC_RSTn: R138.2 U21.K5(RST_N) U25.4(Y)
EXP_GPIO0_14_LT: U12.E18(OSPI0_CSN3) ; also on sheet 34
GPIO_eMMC_RSTn: R141.1 U25.1(A) ; also on sheet 39
GPIO_OSPI_RSTn: R332.1 U8.1(A) U12.F17(OSPI0_CSN1)
MMC0_CLK: R91.1 R400.1 R401.2 U21.M6(CLK)
MMC1_CLK: J21.5(CLK) R49.1 R51.1 R88.1 U15.6(IO4)
MMC1_CLK_R: R49.2 U12.A20(MMC1_CLK)
MMC1_CMD: J21.3(CMD) R73.1 U12.C18(MMC1_CMD) U15.1(IO1)
MMC1_D0: J21.7(DAT0) R90.1 U12.A19(MMC1_DAT0) U15.8(IO6)
MMC1_D1: J21.8(DAT1) R89.1 U12.B19(MMC1_DAT1) U15.7(IO5)
MMC1_D2: J21.1(DAT2) R74.1 U12.B20(MMC1_DAT2) U15.2(IO2)
MMC1_D3: J21.2(CD/DAT3) R75.1 U12.C19(MMC1_DAT3) U15.3(IO3)
MMC1_SD_EN: R462.1 U52.1(A) ; also on sheet 39
MMC1_SD_LS_EN: R61.1 U13.3(ON) U52.4(Y)
MMC1_SDCD: J21.9(CD) R67.1 U12.C15(MMC1_SDCD) U14.5(IO2)
MMC2_CLK: R40.2 R272.1 ; also on sheet 19
MMC2_CMD: U12.C21(MMC2_CMD) ; also on sheet 19
MMC2_D0: U12.B21(MMC2_DAT0) ; also on sheet 19
MMC2_D1: U12.D21(MMC2_DAT1) ; also on sheet 19
MMC2_D2: U12.E19(MMC2_DAT2) ; also on sheet 19
MMC2_D3: U12.E20(MMC2_DAT3) ; also on sheet 19
OSPI0_CSN0: R334.2 U12.F19(OSPI0_CSN0)
OSPI0_LBCLK: R307.2 R318.1
OSPI0_LBCLKO_R: R318.2 U12.G18(OSPI0_LBCLKO)
OSPI_CLK: R309.1 R316.1 U10.B2(CLK)
OSPI_CS: R37.1 R334.1 U10.C2(~{CS})
OSPI_DQ0: R324.1 RA2.4 U10.D3(IO0)
OSPI_DQ1: R326.1 RA2.3 U10.D2(IO1)
OSPI_DQ2: R323.1 RA2.1 U10.C4(IO2/~{WP})
OSPI_DQ3: R325.1 RA2.2 U10.D4(IO3)
OSPI_DQ4: R321.1 RA3.4 U10.D5(IO4)
OSPI_DQ5: R322.1 RA3.2 U10.E3(IO5)
OSPI_DQ6: R320.1 RA3.3 U10.E2(IO6)
OSPI_DQ7: R319.1 RA3.1 U10.E1(IO7)
OSPI_DQS: R308.1 U10.C3(DS)
OSPI_DQS_SOC: R304.1 R305.1 R307.1 R308.2 U12.H20(OSPI0_DQS)
OSPI_RSTn: R35.1 U8.4(Y) U10.A4(~{RESET})
PORz_OUT: U52.6(C) ; also on sheet 1 24 27 42
RESETSTATz: U8.2(B) U25.2(B) U52.3(B) ; also on sheet 1 4 24 27 32 37 38 39 40 41 42
SOC_GPIO1_49: U12.B15(MMC1_SDWP) ; also on sheet 38
SOC_MMC0_CLK: R91.2 U12.Y1(MMC0_CLK)
SOC_MMC0_CMD: R398.2 U12.V3(MMC0_CMD) U21.M5(CMD)
SOC_MMC0_DAT0: R109.2 U12.V2(MMC0_DAT0) U21.A3(DAT0)
SOC_MMC0_DAT1: R111.2 U12.V1(MMC0_DAT1) U21.A4(DAT1)
SOC_MMC0_DAT2: R113.2 U12.W2(MMC0_DAT2) U21.A5(DAT2)
SOC_MMC0_DAT3: R107.2 U12.W1(MMC0_DAT3) U21.B2(DAT3)
SOC_MMC0_DAT4: R108.2 U12.Y2(MMC0_DAT4) U21.B3(DAT4)
SOC_MMC0_DAT5: R110.2 U12.W3(MMC0_DAT5) U21.B4(DAT5)
SOC_MMC0_DAT6: R112.2 U12.W4(MMC0_DAT6) U21.B5(DAT6)
SOC_MMC0_DAT7: R114.2 U12.V4(MMC0_DAT7) U21.B6(DAT7)
SoC_MMC2_CLK: R40.1 U12.E21(MMC2_CLK)
SoC_OSPI_DQ0: RA2.5 U12.F18(OSPI0_D0)
SoC_OSPI_DQ1: RA2.6 U12.G17(OSPI0_D1)
SoC_OSPI_DQ2: RA2.8 U12.F21(OSPI0_D2)
SoC_OSPI_DQ3: RA2.7 U12.F20(OSPI0_D3)
SoC_OSPI_DQ4: RA3.5 U12.G21(OSPI0_D4)
SoC_OSPI_DQ5: RA3.7 U12.H21(OSPI0_D5)
SoC_OSPI_DQ6: RA3.6 U12.G20(OSPI0_D6)
SoC_OSPI_DQ7: RA3.8 U12.J21(OSPI0_D7)
WLAN_EN_SOC: U12.D20(MMC2_SDCD) ; also on sheet 19
WLAN_IRQ: U12.C20(MMC2_SDWP) ; also on sheet 19
N16878497: R124.1 TP43.1(TP) U21.H5(DS)
N22727847: R316.2 U12.G19(OSPI0_CLK)

Not connected (* = marked no-connect by the designer): U10 A2(NC1)* A3(NC2)* A5(NC3)* B1(NC4)* B5(NC5)* C5(NC6)*; U12 E17(OSPI0_CSN2); U13 4(CT)*; U14 2(NC2)* 3(IO1)*; U15 4(NC1)* 9(NC2)*; U21 A1(NC1)* A2(NC2)* A7(RFU1)* A8(NC3)* A9(NC4)* A10(NC5)* A11(NC6)* A12(NC7)* A13(NC8)* A14(NC9)* B1(NC10)* B7(NC11)* B8(NC12)* B9(NC13)* B10(NC14)* B11(NC15)* B12(NC16)* B13(NC17)* B14(NC18)* C1(NC19)* C3(NC20)* C5(NC21)* C7(NC22)* C8(NC23)* C9(NC24)* C10(NC25)* C11(NC26)* C12(NC27)* C13(NC28)* C14(NC29)* D1(NC30)* D2(NC31)* D3(NC32)* D4(NC33)* D12(NC34)* D13(NC35)* D14(NC36)* E1(NC37)* E2(NC38)* E3(NC39)* E5(RFU2)* E8(VSF1)* E9(VSF2)* E10(VSF3)* E12(NC40)* E13(NC41)* E14(NC42)* F1(NC43)* F2(NC44)* F3(NC45)* F10(VSF4)* F12(NC46)* F13(NC47)* F14(NC48)* G1(NC49)* G2(NC50)* G3(NC51)* G10(VSF5)* G12(NC52)* G13(NC53)* G14(NC54)* H1(NC55)* H2(NC56)* H3(NC57)* H12(NC58)* H13(NC59)* H14(NC60)* J1(NC61)* J2(NC62)* J3(NC63)* J12(NC64)* J13(NC65)* J14(NC66)* K1(NC67)* K2(NC68)* K3(NC69)* K6(RFU3)* K7(RFU4)* K10(VSF6)* K12(NC70)* K13(NC71)* K14(NC72)* L1(NC73)* L2(NC74)* L3(NC75)* L12(NC76)* L13(NC77)* L14(NC78)* M1(NC79)* M2(NC80)* M3(NC81)* M7(NC82)* M8(NC83)* M9(NC84)* M10(NC85)* M11(NC86)* M12(NC87)* M13(NC88)* M14(NC89)* N1(NC90)* N3(NC91)* N6(NC92)* N7(NC93)* N8(NC94)* N9(NC95)* N10(NC96)* N11(NC97)* N12(NC98)* N13(NC99)* N14(NC100)* P1(NC101)* P2(NC102)* P7(NC103)* P8(NC104)* P9(NC105)* P10(VSF7)* P11(NC106)* P12(NC107)* P13(NC108)* P14(NC109)*

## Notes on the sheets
sheet 20
- SOC - MMC Interface
- D-Note :-
  0E provision on MMC0_CLK
  Helps improve signal integrity
- eMMC FLASH
- D-Note :-
  MMC0 interface is compliant
  with the JEDEC eMMC electrical
  standard v5.1 (JESD84-B51)
- D-Note :-
  Add additional decaps as required
  Refer SK-AM62P-LP schematics
- D-Note :-
  This family of processor implements a soft PHY for eMMC
  interface. The pulls required for D0, Clock and other
  eMMC interface control signals are recommended to be
  implemented externally.
- D-Note :-
  For D7..D1 eMMC device is expected to have the
  pullups enabled by default.
  The eMMC host/phy disables the eMMC device pullups
  and enables SOC internal pullups.
  Provision for external pullups is optional or the
  pullups can be deleted.
- CAD Note :-
  Place SOC clock output
  pulldown resistor near to
  the clock input pin of the
  attached (memory) device
- R-Note :-
  What is the reason we selected pulldown
  instead of pullup for EMMC,  SD card or
  other peripherals?
  Because there are cases where the clock is
  stopped or paused in a low logic state and
  the pull-down option is consistent with
  this logic state.
- D-Note :-
  Ok to use standard 47K or similar
  resistor for all the parallel pulls
- GPIO1_49
- CAD Note :-
  Place SOC clock output
  pulldown resistor near to
  the clock input pin of
  the attached (memory)
  device
- D-Note :-
  Ensure eMMC_RSTn Reset input is
  enabled in the eMMC device (eMMC
  non-volatile configuration space)
  for the reset logic to be
  functional
- eMMC FLASH RESET
- D-Note :-
  The GPIO reset option makes it possible for
  software to reset the attached device (eMMC or
  OSPI or SD card or OLDI or EPHY) without
  resetting the entire processor if there is a
  case where the peripheral becomes unresponsive.
- D-Note :-
  Add a series resistor to the GPIO
  input for isolation or testing
  Refer SK-AM62P-LP schematics
- D-Note :-
  Ok to use standard 47K
- D-Note :-
  You could eliminate the GPIO option and only use
  the reset output (Warm or Cold), where software
  forces a warm reset if the peripheral becomes
  unresponsive. However, this will reset the entire
  device rather than trying to recover the specific
  peripheral without resetting the entire device.
- D-Note :-
  In case ANDing logic is not used and the
  processor Main Domain warm reset status output
  (RESETSTATz) is used to reset the attached
  device, ensure the IO voltage level of the
  attached device matches the RESETSTATz IO
  voltage level. A level translator is
  recommended to match the IO voltage level.A
  resistor divider could be used alternatively,
  provided optimum impedance value of the
  resistor divider is selected.If too high the
  rise/fall time of the eMMC reset input could be
  slow and introduce too much delay. If too low
  it will cause the AM62x to source too much
  steady-state current during normal operation.
- D-Note :-
  ANDing logic additionally performs level translation
  Verify the Reset IO level compatibility before
  optimizing the reset ANDing logic.
  IO level mismatch could cause supply leakage and
  affect SOC operation
sheet 21
- SD CARD INTERFACE
- D-Note :-
  This power switch, along with the power switch supply reset logic, and the host IO power supply
  circuit is required to support UHS-I SD Cards which begins communications
   using 3.3V signal levels and later change to 1.8V signal levels when changing to one of the
  faster data transfer speeds.
  Cycling power to the SD Card is the only way to put it back into 3.3V mode since SD Cards do
  not have a reset pin.
  The host IO power supply must power off/on and change voltage at the same time as the SD Card.
  These circuits and the software driver operating
   the signals sourcing these circuits ensure both devices are off, or on and operating at the
  same IO voltage at the same time.
- SD CARD LOAD SWITCH RESET LOGIC
- LOAD SWITCH
- D-Note :-
  Add a series resistor to the GPIO input
  for isolation or testing
  Refer SK-AM62P-LP schematics
- D-Note :-
  Anding logic could be optimized to 2
  input AND gate
  Use RESETSTATz and the SoC IO as inputs
- D-Note :-
  CT - Add a 220 pF or higher cap for
  SD card supply slew rate control
- Note :-
  MMC1_CLK pullup is a DNI
- D-Note :-
  For UHS-I  operation, the pullups
  are recommended to be connected to
  the 3.3V/1.8V switched LDO output
- D-Note :-
  Ensure internal pullups are not configured when 10K
  external pullups are used. As a good design practice, a
  47K pullup is recommended to ensure the pullup value is
  within the SD card specification, when internal pulls are
  enabled unexpectedly. This way the resulting pull
  resistance will still be within the specified.
- D-Note :-
  Add a filter cap
- CAD Note :-
  Place near SD Card Connector
sheet 22
- OSPI  FLASH
- D-Note :-
  These 0R resistors are used for configuring QSPI and OSPI
  This is optional during custom board design
- D-Note :-
  Connecting OSPI interface to multiple devices
  is not recommended or supported
- R-Note
  SOC IO buffers are off during power-up. A pullup
  is recommended near to the attached device, to
  hold the attached device IOs in a known state.
  Use of Pullups are attached device dependent
- SOC OSPI INTERFACE
- D-Note :-
  For QSPI Configuration
  Remove 0E resistors from the following
  1.OSPI_DQ4 to OSPI_DQ7 nets (RA3)
- D-Note :-
  External loopback clock series resistors
  are DNI when DQS is connected
- R-Note :-
  DQS pulldown is enabled
- CAD Note :-
  Place SOC clock output
  pulldown resistor near to
  the clock input pin of the
  attached (memory) device
- CAD Note:- Place R307 close to the
  Memory to avoid stub
- CAD Note:- Place R318 close to the SOC Ball
  with as little trace as possible
- CAD -Note :-
  Place pulldown closer to the SoC
- D-Note :-
  Choice of QSPI memory device :
  For improved performance, it is recommended to select
  QSPI memory device with an external reset input pin. The
  reset pin is recommended to be controlled using SOC
  reset status output or an ANDing logic as implemented in
  the starter kit
- OSPI  FLASH RESET
- D-Note :-
  Add a series resistor to the GPIO input
  for isolation or testing
  Refer SK-AM62P-LP schematics
- D-Note :-
  ANDing logic additionally performs level translation
  Verify the Reset IO level compatibility before
  optimizing the reset ANDing logic.
  IO level mismatch could cause supply leakage and
  affect SOC operation
